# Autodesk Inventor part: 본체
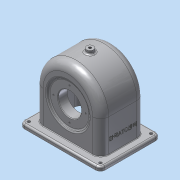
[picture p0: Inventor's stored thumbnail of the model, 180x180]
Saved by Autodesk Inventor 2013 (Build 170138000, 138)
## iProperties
Created: 2016-01
Part Number: 본체
Material: 알루미늄 6061
Document SubType Name: Modeling
Designer: Administrator
Mass: 874.696 g
Surface Area: 1049.39 cm^2
Volume: 322.766 cm^3
Density: 2.71 g/cm^3
Author: Administrator
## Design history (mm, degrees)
sketch "스케치1"
  geometry: L1 (-52, 70)-(52, 70); L2 (52, 70)-(52, -70); L3 (52, -70)-(-52, -70); L4 (-52, -70)-(-52, 70); 3 further points
  constraints: 8 end point, 2 midpoint, 2 parallel, 1 horizontal, 1 horizontal alignment, 1 perpendicular, 1 vertical alignment
  dimensions: "d0" = 104 distance of L1.start L1.end; "d2" = 140 distance of L1.end L2.end
extrude "돌출1" new body sketch "스케치1" distance "d3" = 7; taper "d4" = 0 deg
sketch "스케치2"
  geometry: L1 (-70, 0)-(70, 0) reference; L2 (-70, 0)-(-70, 7) reference; L3 (70, 7)-(-70, 7) reference; L4 (70, 0)-(70, 7) reference; L5 (-57, 64)-(-57, 0); L6 (57, 64)-(57, 0); L7 (-57, 0)-(57, 0); A1 r 57 centre (0, 64) between (-57, 64) and (57, 64); 2 further points
  constraints: 6 end point, 2 perpendicular, 2 point on circle, 2 point on line, 2 tangent, 1 centre point, 1 collinear, 1 midpoint, 1 vertical alignment
  dimensions: "d5" = 114 diameter of A1; "d7" = 64 distance of A1.centre point (0, 0)
  node "투영된 루프1"
extrude "돌출2" join sketch "스케치2" stored distance "d8" = 77; taper "d9" = 0 deg
sketch "스케치5"
  geometry: L1 (-57, 7)-(57, 7) reference; L2 (-57, 7)-(-57, 64) reference; L3 (57, 64)-(57, 7) reference; L4 (-70, 0)-(70, 0) reference; L5 (-70, 0)-(-70, 7) reference; L6 (70, 7)-(-70, 7) reference; L7 (70, 0)-(70, 7) reference; L8 (-51, 64)-(-51, 0); L9 (51, 64)-(51, 0); L10 (-51, 0)-(51, 0); A1 r 57 centre (0, 64) between (57, 64) and (-57, 64) reference; A2 r 51 centre (0, 64) between (51, 64) and (-51, 64); 1 further point
  constraints: 6 end point, 2 perpendicular, 2 point on circle, 2 point on line, 2 tangent, 1 centre point, 1 coincident, 1 parallel
  dimensions: "d12" = 102 diameter of A2
extrude "돌출3" cut sketch "스케치5" stored distance "d14" = 67; taper "d15" = 0 deg
sketch "스케치6"
  geometry: L1 (-38.5, 121)-(-38.5, 64) reference; L2 (-38.5, 64)-(-38.5, 7) reference; L3 (-33.5, 64)-(-33.5, 0) reference; L4 (-33.5, 115)-(-33.5, 64) reference; L5 (38.5, 64)-(38.5, 121) reference; L6 (38.5, 121)-(-38.5, 121) reference; L7 (33.5, 64)-(33.5, 115) reference; L8 (33.5, 115)-(-33.5, 115) reference; L9 (33.5, 0)-(33.5, 64) reference; L10 (38.5, 7)-(38.5, 64) reference; L11 (-72.8, 0)-(72.8, 0) reference; L12 (52, 7)-(-52, 7) reference; L13 (52, 0)-(52, 7) reference; L14 (-52, 0)-(-52, 7) reference; L15 (-38.5, 60)-(38.5, 60); L16 (-19.5, 60)-(-19.5, 88); L17 (-19.5, 88)-(-38.5, 103.943); L18 (-38.5, 60)-(-19.5, 60); L19 (-38.5, 103.943)-(-38.5, 60); 1 further point
  constraints: 10 end point, 4 point on line, 2 collinear, 2 perpendicular
  dimensions: "d16" = 60 distance from line of L11 L15.start; "d17" = 50 deg angle of L17 L16; "d18" = 28 distance of L16.start L16.end; "d19" = 19 distance between parallel lines of L19 L16
revolve "회전1" stored, may be unused: angle "d20" = 90 deg
sketch "스케치9"
  geometry: L1 (-38.5, 64)-(-38.5, 7) reference; L2 (-52, 0)-(52, 0) reference; L3 (-52, 0)-(-52, 7) reference; L4 (52, 7)-(-52, 7) reference; L5 (52, 0)-(52, 7) reference; L6 (38.5, 7)-(38.5, 64) reference; L7 (38.5, 64)-(38.5, 121) reference; L8 (38.5, 121)-(-38.5, 121) reference; L9 (-33.5, 99.747)-(-33.5, 20.253) reference; L10 (-19.5, 32)-(-19.5, 88) reference; L11 (-33.5, 99.747)-(-33.5, 20.253) reference; L12 (-33.5, 99.747)-(-19.5, 88) reference; L13 (33.5, 0)-(-33.5, 0) reference; L14 (33.5, 0)-(33.5, 64) reference; L15 (-33.5, 64)-(33.5, 64) reference; L16 (-33.5, 64)-(-33.5, 0) reference; L17 (-33.5, 20.253)-(-19.5, 32) reference; L18 (-38.5, 121)-(-38.5, 64) reference; L19 (-38.5, 60)-(38.5, 60); L20 (-35.5, 94.899)-(-35.5, 60); L21 (-38.5, 97.416)-(-35.5, 94.899); L22 (-35.5, 60)-(-38.5, 60); L23 (-38.5, 60)-(-38.5, 97.416); 1 further point
  constraints: 10 end point, 4 point on line, 2 collinear, 2 perpendicular, 1 parallel
  dimensions: "d23" = 60 vertical distance of L2.start L19.start; "d25" = 3 distance between parallel lines of L18 L20; "d26" = 5 distance between parallel lines of L12 L21
revolve "회전2" sketch "스케치9" stored, may be unused: angle "d27" = 90 deg
node "작업 평면1"
sketch "스케치11"
  geometry: C1 r 6 at (0, 0); 1 further point
  constraints: 1 centre point, 1 coincident
  dimensions: "d29" = 12 diameter of C1
extrude "돌출4" join sketch "스케치11" stored distance "d30" = 67; taper "d31" = 0 deg
sketch "스케치20"
  geometry: C1 r 28 at (0, 0) reference; C2 r 20 at (0, 0); 1 further point
  constraints: 1 centre point, 1 coincident
  dimensions: "d61" = 40 diameter of C2
extrude "돌출7" cut sketch "스케치20" distance "d62" = 19; taper "d63" = 0 deg
hole "구멍3" diameter "d66" = 4.459; stored, may be unused: countersink angle "d70" = 90 deg, drill point angle "d72" = 118 deg; dims "d64" = 10, "d65" = 10, "d67" = 20, "d68" = 4, "d69" = 2, "d71" = 9
sketch "스케치21"
  geometry: L1 (77, -15.584)-(77, -90.416) reference; L2 (0, 0)-(0, -57) reference; L3 (77, -57)-(77, 0) reference; L4 (90.5, 7)-(-13.5, 7) reference; L5 (90.5, 7)-(90.5, 0) reference; L6 (-13.5, 0)-(90.5, 0) reference; L7 (-13.5, 7)-(-13.5, 0) reference; L8 (63.387, -26.602)-(13.613, -26.602); L9 (13.613, -26.602)-(13.613, -19.398); L10 (13.613, -19.398)-(63.387, -19.398); L11 (63.387, -19.398)-(63.387, -26.602); 4 further points
  constraints: 2 midpoint, 1 horizontal alignment, 1 vertical alignment, 2 other
  dimensions: "d74" = 38.5 distance from line of point (38.5, -23) L3; "d75" = 30 distance from line of L4 point (38.5, -23)
feature "엠보싱1" sketch "스케치21" dims "d0" = 104, "d2" = 140, "d76" = 0.5, "d77" = 0
sketch "스케치22"
  geometry: L1 (-33.5, 51)-(-33.5, -51) reference; L2 (-33.5, -51)-(33.5, -51) reference; L3 (33.5, -51)-(33.5, 51) reference; L4 (33.5, 51)-(-33.5, 51) reference; L5 (-52, 70)-(52, 70) reference; L6 (52, 70)-(52, -70) reference; L7 (52, -70)-(-52, -70) reference; L8 (-52, -70)-(-52, 70) reference; 5 further points
  constraints: 2 horizontal alignment, 2 vertical alignment
  dimensions: "d78" = 8 distance from line of L6 point (44, -62); "d79" = 44 horizontal distance of point (0, 0) point (-44, -62); "d80" = 8 distance from line of point (-44, -62) L7; "d81" = 124 distance of point (-44, 62) point (-44, -62)
hole "구멍4" sketch "스케치22" at (44, -62), (-44, -62), (-44, 62), (44, 62) diameter "d82" = 5; stored, may be unused: countersink angle "d86" = 90 deg, drill point angle "d88" = 118 deg; dims "d83" = 20, "d84" = 4, "d85" = 2, "d87" = 9
fillet "모깎기1" dims "d89" = 8
fillet "모깎기2" dims "d90" = 3
fillet "모깎기3" dims "d91" = 3
fillet "모깎기4" dims "d92" = 14
fillet "모깎기5" dims "d93" = 9
chamfer "모따기1" distance "d94" = 1; stored, may be unused: second distance "d95" = 2, angle "d96" = 45 deg
fillet "모깎기6" dims "d97" = 1
fillet "모깎기8" dims "d99" = 3
sketch "스케치25" dims "d101" = 56
  geometry: C1 r 21 at (-60, 0) reference; C2 r 33.5 at (-60, 0) reference; 3 further points
  constraints: 2 horizontal alignment, 1 coincident, 2 other
hole "구멍5" sketch "스케치25" at (-88, 0) diameter "d102" = 2.459; stored, may be unused: countersink angle "d106" = 90 deg, drill point angle "d108" = 118 deg; dims "d103" = 10, "d104" = 4, "d105" = 2, "d107" = 12
sketch "스케치26"
  geometry: C1 r 31 at (60, 0); 1 further point
  constraints: 1 centre point, 1 horizontal alignment
  dimensions: "d112" = 60 distance of C1.centre point (0, 0); "d113" = 62 diameter of C1
extrude "돌출8" join sketch "스케치26" distance "d114" = 10; taper "d115" = 0 deg
sketch "스케치27"
  geometry: C1 r 31 at (0, 0) reference; C2 r 20 at (0, 0); 1 further point
  constraints: 1 centre point, 1 coincident
  dimensions: "d116" = 40 diameter of C2
extrude "돌출9" cut sketch "스케치27" distance "d117" = 15; taper "d118" = 0 deg
sketch "스케치28" dims "d120" = 48
  geometry: C1 r 20 at (0, 0) reference; 3 further points
  constraints: 2 horizontal alignment, 1 coincident, 2 other
hole "구멍6" sketch "스케치28" at (24, 0) diameter "d121" = 2.459; stored, may be unused: countersink angle "d125" = 90 deg, drill point angle "d127" = 118 deg; dims "d122" = 6, "d123" = 4, "d124" = 2, "d126" = 8
fillet "모깎기9" dims "d131" = 3
chamfer "모따기2" distance "d132" = 1; stored, may be unused: second distance "d133" = 2, angle "d134" = 45 deg
node "솔리드1"
pattern_circular "원형 패턴3" dims angle "d110" = 360 deg
pattern_circular "원형 패턴4" dims angle "d129" = 360 deg
node "투영된 루프3"
node "투영된 루프4"
node "투영된 루프6"
node "투영된 루프7"
node "투영된 루프8"
node "투영된 루프11"
node "투영된 루프12"
node "투영된 루프14"
other parameters: "d24" = 5, "d28" = 127
